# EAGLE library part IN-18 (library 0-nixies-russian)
IN-18: large numeric frontview nixie tube
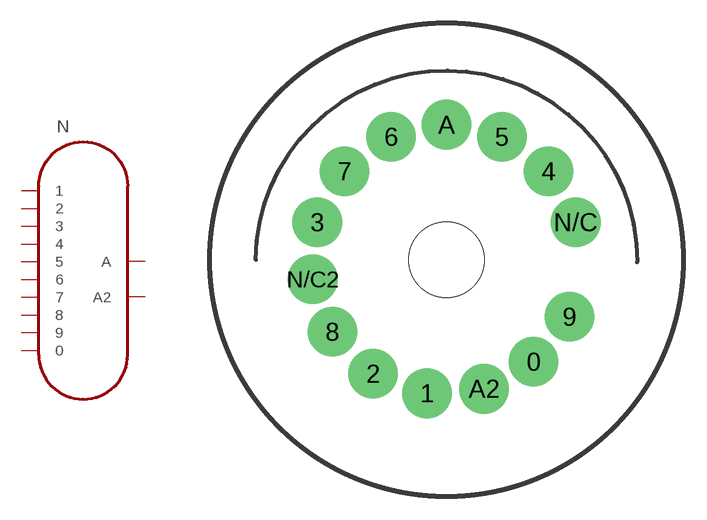
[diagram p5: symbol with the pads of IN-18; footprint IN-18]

Designator prefix N

## IN-18  [IN-18]
0  0
1  1
2  2
3  3
4  4
5  5
6  6
7  7
8  8
9  9
A  A
A2  A2

## Footprint IN-18 (pad centres in mm)
May be used with socket: PL31-P
drill 2.3 pad 3.2 round: 0 5.8,-6.8; 1 -1.3,-8.9; 2 -4.9,-7.6; 3 -8.6,2.5; 4 6.8,5.9; 5 3.7,8.2; 6 -3.7,8.2; 7 -6.8,5.9; 8 -7.6,-4.8; 9 8.2,-3.8; A 0,9; A2 2.5,-8.6; N/C 8.6,2.5; N/C2 -8.9,-1.3
hole 5 at 0,0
